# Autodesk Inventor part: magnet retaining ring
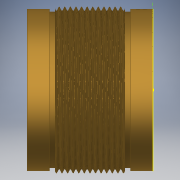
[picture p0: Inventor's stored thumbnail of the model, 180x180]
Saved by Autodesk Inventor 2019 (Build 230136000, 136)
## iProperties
Created: 2019-05
Part Number: magnet retaining ring
Material: Brass, Soft Yellow
Document SubType Name: Modeling
Designer: Chloe
Density: 8.47 g/cm^3
Appearance: Brass - Satin
Author: Chloe
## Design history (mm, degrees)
sketch "Sketch1"
  geometry: C1 r 29 at (0, 0); 1 further point
  constraints: 1 centre point, 1 coincident
  dimensions: "d0" = 58 diameter of C1
extrude "Extrusion1" new body sketch "Sketch1" distance "d1" = 8; taper "d2" = 0 deg
sketch "Sketch4"
  geometry: C1 r 28 at (0, 0); 1 further point
  constraints: 1 centre point, 1 coincident
  dimensions: "d11" = 56 diameter of C1
extrude "Extrusion4" join sketch "Sketch4" distance "d12" = 2; taper "d13" = 0 deg
sketch "Sketch5"
  geometry: C1 r 29.84 at (0, 0); 2 further points
  constraints: 1 centre point, 1 coincident
  dimensions: "d40" = 59.68 diameter of C1
extrude "Extrusion5" join sketch "Sketch5" distance "d14" = 25; taper "d15" = 0 deg
sketch "Sketch6"
  geometry: C1 r 28 at (0, 0); 1 further point
  constraints: 1 centre point, 1 coincident
  dimensions: "d19" = 56 diameter of C1
extrude "Extrusion6" join sketch "Sketch6" distance "d20" = 2; taper "d21" = 0 deg
sketch "Sketch7"
  geometry: C1 r 29 at (0, 0); 1 further point
  constraints: 1 centre point, 1 coincident
  dimensions: "d30" = 58 diameter of C1
extrude "Extrusion7" join sketch "Sketch7" distance "d22" = 8; taper "d23" = 0 deg
sketch "Sketch8"
  geometry: C1 r 14.525 at (0, 0); 1 further point
  constraints: 1 centre point, 1 coincident
  dimensions: "d24" = 29.05 diameter of C1
extrude "Extrusion8" cut sketch "Sketch8" extent not by distance; stored distance "d25" = 8; taper "d26" = 0 deg
sketch "Sketch9"
  geometry: C1 r 24.525 at (0, 0); 1 further point
  constraints: 1 centre point, 1 coincident
  dimensions: "d27" = 49.05 diameter of C1
extrude "Extrusion9" cut sketch "Sketch9" distance "d28" = 40; taper "d29" = 0 deg
sketch "Sketch10"
  geometry: 3 further points
  constraints: 1 horizontal alignment, 1 other
workplane "Work Plane1"
sketch "Sketch14"
  geometry: L1 (0, 29)-(0, -29) reference; L2 (0, 29)-(0, -29) reference; L3 (8, -29)-(8, 29) reference; L4 (0, 29)-(0, -29) reference; L5 (8, -29)-(8, 29) reference; 2 further points
  dimensions: "d31" = 4 distance from line of L1 point (4, 0)
hole "Hole1" sketch "Sketch14" at (4, 0) diameter "d32" = 4; stored, may be unused: countersink angle "d36" = 82 deg, drill point angle "d38" = 118 deg; dims "d33" = 8.001, "d34" = 9.525, "d35" = 6.35, "d37" = 11.811
thread "Thread3" dims "d41" = 25.4, "d42" = 0
thread "Thread4" dims "d100" = 25.4, "d101" = 0
sketch "Sketch25"
  geometry: L1 (29.84, 0)-(29.84, 25); L2 (29.84, 25)-(28.357, 25); L3 (28.357, 25)-(28.357, 0); L4 (28.357, 0)-(29.84, 0); L5 (0, -19)-(0, 44) reference
  constraints: 8 end point
revolve "Revolution7" sketch "Sketch25" stored, may be unused: angle "d111" = 0 deg
sketch "Sketch26"
  geometry: L1 (29.84, 0)-(29.84, 25); L2 (29.84, 25)-(28.357, 25); L3 (28.357, 25)-(28.357, 0); L4 (28.357, 0)-(29.84, 0); L5 (0, -19)-(0, 44) reference
  constraints: 8 end point
revolve "Revolution8" sketch "Sketch26" stored, may be unused: angle "d112" = 0 deg
sketch "Sketch24"
  geometry: L1 (-1.167, -28.458)-(-1, -28.458); L2 (0.167, -29.739)-(0, -30.059); L3 (-2, -30.059)-(-2.167, -29.739); L4 (-0.833, -28.458)-(-1, -28.138); L5 (-1, -28.138)-(-1.167, -28.458); L6 (-2, -30.059)-(-1.833, -29.739); L7 (-0.833, -28.458)-(-0.167, -29.739); L8 (-2.167, -29.739)-(-1.833, -29.739); L9 (0.167, -29.739)-(-0.167, -29.739); L10 (-2, -30.059)-(-2, -29.739); L11 (0, -30.059)-(0, -29.739); L12 (-1, -28.138)-(-1, -28.357); L13 (-2, -29.84)-(0, -29.84); L14 (-0.167, -29.739)-(0, -30.059); L15 (-1.833, -29.739)-(-1.167, -28.458); L16 (0, 0)-(0, 0.018); L17 (0, 0.018)-(0, 0); L18 (0, 0)-(0.033, 0); L19 (-1, -28.357)-(-1, -28.458); L20 (-1, -28.458)-(-0.833, -28.458); A1 r 0.188 centre (-2, -29.652) between (-2.167, -29.739) and (-2, -29.84); A2 r 0.188 centre (-2, -29.652) between (-2, -29.84) and (-1.833, -29.739); A3 r 0.188 centre (0, -29.652) between (-0.167, -29.739) and (0, -29.84); A4 r 0.188 centre (0, -29.652) between (0, -29.84) and (0.167, -29.739); A5 r 0.188 centre (-1, -28.545) between (-1, -28.357) and (-1.167, -28.458); A6 r 0.188 centre (-1, -28.545) between (-0.833, -28.458) and (-1, -28.357)
  constraints: 40 end point, 12 point on circle, 10 parallel, 8 tangent, 6 centre point, 6 collinear, 2 midpoint, 2 point on line, 1 horizontal, 1 perpendicular, 3 other
  dimensions: "d102" = 55 deg angle of L7 L15 (= d109); "d103" = 0.32017 distance of L4.end L1.end (= 0.160083 x Sketch24_Pitch); "d104" = 0.32017 distance of L2.end L11.end (= 0.160083 x Sketch24_Pitch); "Sketch24_ThreadOffset" = 0 distance between parallel lines of L16 L11; "Sketch24_MajorRadius" = 29.84 distance from line of L13 L16.start; "d107" = 2 distance from line of L2.end L10 (= Sketch24_Pitch); "Sketch24_MinorRadius" = 28.35708 distance edge to line of A6 L18 (derived)
coil "Coil4" sketch "Sketch24" pitch "d113" = 2.002; turns "d115" = 1; dims "d114" = 29, "d116" = 0, angle "d117" = 0 deg, angle "d118" = 0 deg, "d119" = 0, "d120" = 0
sketch "Sketch28"
  geometry: L1 (2, 0)-(2, 4.557); L2 (2, 4.557)-(1.481, 4.557); L3 (1.481, 4.557)-(1.481, 0); L4 (1.481, 0)-(2, 0); L5 (0, -12.776)-(0, 70.776) reference
  constraints: 8 end point
revolve "Revolution9" sketch "Sketch28" stored, may be unused: angle "d130" = 0 deg
sketch "Sketch27"
  geometry: L1 (-0.408, -0.036)-(-0.35, -0.036); L2 (0.058, -0.484)-(0, -0.596); L3 (-0.7, -0.596)-(-0.758, -0.484); L4 (-0.292, -0.036)-(-0.35, 0.076); L5 (-0.35, 0.076)-(-0.408, -0.036); L6 (-0.7, -0.596)-(-0.642, -0.484); L7 (-0.292, -0.036)-(-0.058, -0.484); L8 (-0.758, -0.484)-(-0.642, -0.484); L9 (0.058, -0.484)-(-0.058, -0.484); L10 (-0.7, -0.596)-(-0.7, -0.484); L11 (0, -0.596)-(0, -0.484); L12 (-0.35, 0.076)-(-0.35, 0); L13 (-0.7, -0.519)-(0, -0.519); L14 (-0.058, -0.484)-(0, -0.596); L15 (-0.642, -0.484)-(-0.408, -0.036); L16 (0, 0)-(0, 0.018); L17 (0, 0.018)-(0, 0); L18 (0, 0)-(0.033, 0); L19 (-0.35, 0)-(-0.35, -0.036); L20 (-0.35, -0.036)-(-0.292, -0.036); A1 r 0.066 centre (-0.7, -0.453) between (-0.758, -0.484) and (-0.7, -0.519); A2 r 0.066 centre (-0.7, -0.453) between (-0.7, -0.519) and (-0.642, -0.484); A3 r 0.066 centre (0, -0.453) between (-0.058, -0.484) and (0, -0.519); A4 r 0.066 centre (0, -0.453) between (0, -0.519) and (0.058, -0.484); A5 r 0.066 centre (-0.35, -0.066) between (-0.35, 0) and (-0.408, -0.036); A6 r 0.066 centre (-0.35, -0.066) between (-0.292, -0.036) and (-0.35, 0)
  constraints: 40 end point, 12 point on circle, 10 parallel, 8 tangent, 6 centre point, 6 collinear, 2 midpoint, 2 point on line, 1 horizontal, 1 perpendicular, 3 other
  dimensions: "d121" = 55 deg angle of L7 L15 (= d128); "d122" = 0.11206 distance of L4.end L1.end (= 0.160083 x Sketch27_Pitch); "d123" = 0.11206 distance of L2.end L11.end (= 0.160083 x Sketch27_Pitch); "Sketch27_ThreadOffset" = 0 distance between parallel lines of L16 L11; "Sketch27_MajorRadius" = 0.51902 distance from line of L13 L16.start; "d126" = 0.7 distance from line of L2.end L10 (= Sketch27_Pitch); "Sketch27_MinorRadius" = 0 distance edge to line of A6 L18 (derived)
coil "Coil5" sketch "Sketch27" pitch "d131" = 0.7007; turns "d133" = 1; dims "d132" = 5.95669, "d134" = 0, angle "d135" = 0 deg, angle "d136" = 0 deg, "d137" = 0, "d138" = 0
body "Solid1"
node "Projected Loop1"
node "Projected Loop2"
body "Solid5"
body "Solid6"
other parameters: "d50" = 55 deg [user parameter], "Sketch15_Pitch" = 2 [user parameter], "d69" = 55 deg [user parameter], "Sketch18_Pitch" = 2 [user parameter], "d88" = 55 deg [user parameter], "Sketch21_Pitch" = 2 [user parameter], "d109" = 55 deg [user parameter; used in 1 equation term], "Sketch24_Pitch" = 2 [user parameter; used in 3 equation terms], "d128" = 55 deg [user parameter; used in 1 equation term], "Sketch27_Pitch" = 0.7 [user parameter; used in 3 equation terms]
